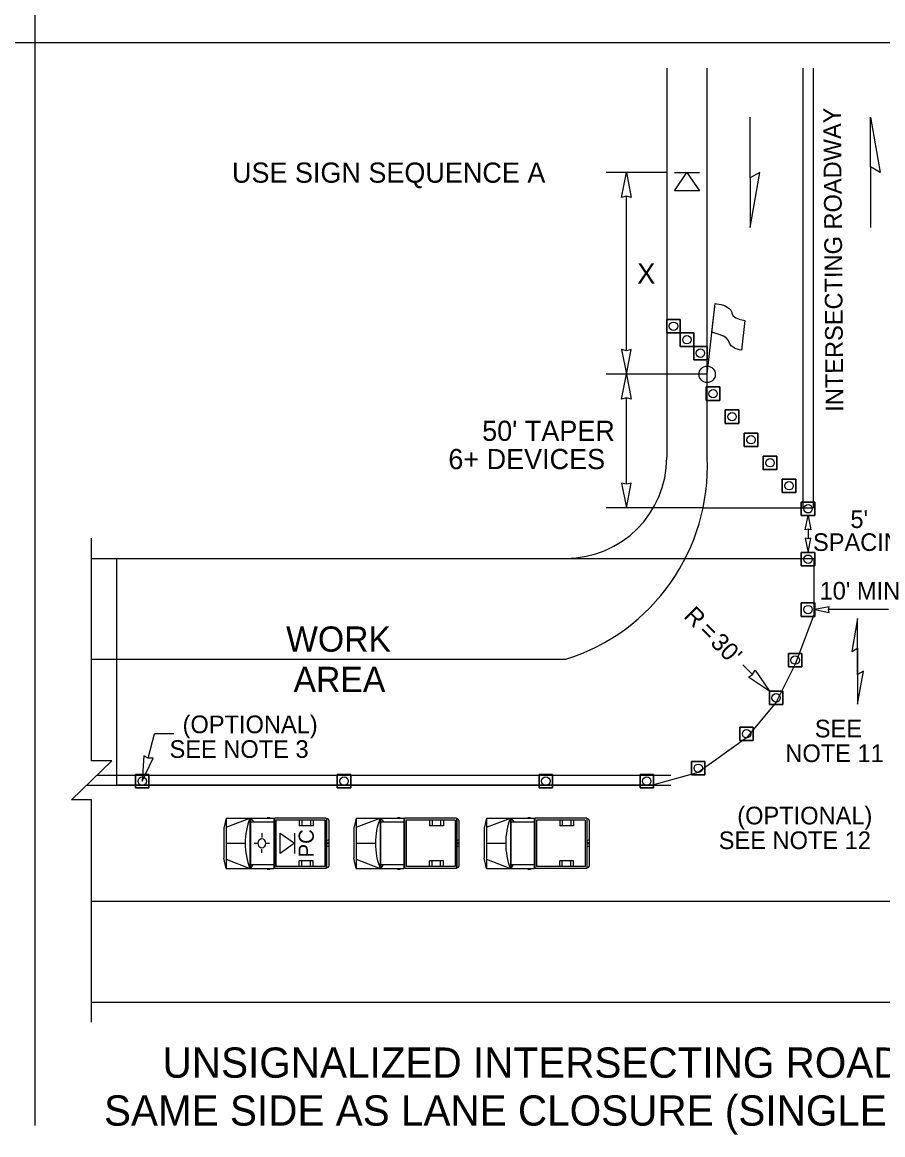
# Model space of a CAD drawing. Extents: x 99999.1 to 100095.7, y 99995 to 100010.7.
# Drawn here: x 100025.2 to 100028.611, y 100001.65 to 100006.062 of the extents above; entities that cross this region are included whole.
import ezdxf

# ---------------------------------------------------------------- set-up
doc = ezdxf.new("R2010")
doc.units = 0
for name, color, linetype in [('RD_ED_ShoulderPavedEdge', 7, 'Continuous'), ('RD_MK_LineDblYellowCenter', 7, 'Continuous'), ('RD_MK_LineEdgeWhite', 7, 'Continuous'), ('RD_MK_LineStop', 7, 'Continuous'), ('SH_DE_DetailBody1Text', 7, 'Continuous'), ('SH_DE_DetailHeading2Text', 7, 'Continuous'), ('TR_WZ_FlaggingStation', 7, 'Continuous'), ('TR_WZ_MotoristVehicle', 7, 'Continuous'), ('TR_WZ_PortableSignMountBlk-Org', 7, 'Continuous'), ('TR_WZ_PortableSignMountBlk-Wht', 7, 'Continuous'), ('TR_WZ_TrafficCone', 7, 'Continuous'), ('TR_WZ_WorkAreaLabel', 7, 'Continuous'), ('TR_WZ_WorkZoneDetails', 7, 'Continuous'), ('TR_WZ_WorkZoneTextCurrent', 7, 'Continuous')]:
    doc.layers.add(name, color=color, linetype=linetype)

msp = doc.modelspace()

# ---------------------------------------------------------------- linework, layer by layer
at = {"layer": 'RD_ED_ShoulderPavedEdge'}
for p, q in [((100025.475, 100003.9359), (100027.355, 100003.9359)), ((100025.475, 100002.1759), (100030.275, 100002.1759))]:
    msp.add_line(p, q, dxfattribs=at)
msp.add_lwpolyline([(100027.755, 100005.8804), (100027.755, 100004.3359)], dxfattribs=at)
msp.add_arc((100027.355, 100004.3359), 0.4, 270, 0, dxfattribs=at)
at = {"layer": 'RD_MK_LineDblYellowCenter'}
for p, q in [((100028.295, 100005.8804), (100028.295, 100004.1359)), ((100028.335, 100005.8804), (100028.335, 100004.1359)), ((100025.4957, 100003.0759), (100027.7712, 100003.0759)), ((100025.4543, 100003.0359), (100027.7712, 100003.0359))]:
    msp.add_line(p, q, dxfattribs=at)
at = {"layer": 'RD_MK_LineEdgeWhite'}
for p, q in [((100027.915, 100004.3359), (100027.915, 100005.8804)), ((100025.475, 100003.5359), (100027.355, 100003.5359)), ((100025.475, 100002.5759), (100030.275, 100002.5759))]:
    msp.add_line(p, q, dxfattribs=at)
msp.add_arc((100027.1158, 100004.2993), 0.8, 287.3948, 2.6212, dxfattribs=at)
at = {"layer": 'RD_MK_LineStop'}
msp.add_line((100027.899, 100004.1359), (100028.335, 100004.1359), dxfattribs=at)
at = {"layer": 'TR_WZ_FlaggingStation'}
for p, q in [((100027.915, 100004.6659), (100027.9471, 100004.9468)), ((100027.934, 100004.8328), (100027.9471, 100004.9471)), ((100028.065, 100004.8793), (100028.0517, 100004.7621)), ((100027.934, 100004.8328), (100027.934, 100004.8328))]:
    msp.add_line(p, q, dxfattribs=at)
for points in [[(100027.9471, 100004.9471), (100027.9528, 100004.9459), (100027.9707, 100004.9424), (100027.9845, 100004.9383), (100027.9942, 100004.9322), (100028.0027, 100004.9275), (100028.0084, 100004.9206), (100028.0126, 100004.9128), (100028.0131, 100004.9066), (100028.0185, 100004.8974), (100028.0293, 100004.8899), (100028.0417, 100004.8847), (100028.065, 100004.8793)], [(100028.0517, 100004.7621), (100028.0436, 100004.7636), (100028.0259, 100004.7682), (100028.0103, 100004.7787), (100028.0037, 100004.7893), (100027.9998, 100004.7996), (100027.9907, 100004.8105), (100027.9798, 100004.8167), (100027.9624, 100004.8238), (100027.934, 100004.8328)]]:
    msp.add_lwpolyline(points, dxfattribs=at)
msp.add_circle((100027.915, 100004.6659), 0.0325, dxfattribs=at)
at = {"layer": 'TR_WZ_MotoristVehicle'}
for p, q in [((100026.008, 100002.9059), (100025.9987, 100002.8655)), ((100026.008, 100002.9059), (100026.008, 100002.7059)), ((100026.008, 100002.9059), (100026.1969, 100002.9059)), ((100026.008, 100002.8693), (100026.1025, 100002.9059)), ((100026.1025, 100002.9059), (100026.1025, 100002.7059)), ((100026.1042, 100002.9059), (100026.1042, 100002.7059)), ((100026.1042, 100002.9059), (100026.1162, 100002.8904)), ((100026.1042, 100002.8904), (100026.1969, 100002.8904)), ((100026.1712, 100002.9087), (100026.1825, 100002.9087)), ((100026.1969, 100002.9059), (100026.1969, 100002.7059)), ((100026.4054, 100002.9059), (100026.1997, 100002.9059)), ((100026.1997, 100002.9059), (100026.1997, 100002.7059)), ((100026.3995, 100002.8979), (100026.2055, 100002.8979)), ((100026.2055, 100002.8979), (100026.2055, 100002.7139)), ((100026.2982, 100002.8979), (100026.2982, 100002.8749)), ((100026.3082, 100002.8979), (100026.3082, 100002.8749)), ((100026.3422, 100002.8979), (100026.3422, 100002.8749)), ((100026.3532, 100002.8979), (100026.3532, 100002.8749)), ((100026.3995, 100002.8979), (100026.3995, 100002.7139)), ((100026.4054, 100002.9059), (100026.4054, 100002.7059)), ((100026.4105, 100002.9026), (100026.4061, 100002.9026)), ((100026.4061, 100002.9026), (100026.4061, 100002.7092)), ((100026.415, 100002.8965), (100026.415, 100002.7153)), ((100026.5243, 100002.9059), (100026.515, 100002.8655)), ((100026.5243, 100002.9059), (100026.5243, 100002.7059)), ((100026.5243, 100002.9059), (100026.7132, 100002.9059)), ((100026.5243, 100002.8693), (100026.6187, 100002.9059)), ((100026.6187, 100002.9059), (100026.6187, 100002.7059)), ((100026.6204, 100002.9059), (100026.6204, 100002.7059)), ((100026.6204, 100002.9059), (100026.6325, 100002.8904)), ((100026.6204, 100002.8904), (100026.7132, 100002.8904)), ((100026.6874, 100002.9087), (100026.6987, 100002.9087)), ((100026.7132, 100002.9059), (100026.7132, 100002.7059)), ((100026.9216, 100002.9059), (100026.7159, 100002.9059)), ((100026.7159, 100002.9059), (100026.7159, 100002.7059)), ((100026.9158, 100002.8979), (100026.7218, 100002.8979)), ((100026.7218, 100002.8979), (100026.7218, 100002.7139)), ((100026.8145, 100002.8979), (100026.8145, 100002.8749)), ((100026.8244, 100002.8979), (100026.8244, 100002.8749)), ((100026.8585, 100002.8979), (100026.8585, 100002.8749)), ((100026.8694, 100002.8979), (100026.8694, 100002.8749)), ((100026.9158, 100002.8979), (100026.9158, 100002.7139)), ((100026.9216, 100002.9059), (100026.9216, 100002.7059)), ((100026.9268, 100002.9026), (100026.9223, 100002.9026)), ((100026.9223, 100002.9026), (100026.9223, 100002.7092)), ((100026.9313, 100002.8965), (100026.9313, 100002.7153)), ((100027.0405, 100002.9059), (100027.0313, 100002.8655)), ((100027.0405, 100002.9059), (100027.0405, 100002.7059)), ((100027.0405, 100002.9059), (100027.2294, 100002.9059)), ((100027.0405, 100002.8693), (100027.135, 100002.9059)), ((100027.135, 100002.9059), (100027.135, 100002.7059)), ((100027.1367, 100002.9059), (100027.1367, 100002.7059)), ((100027.1367, 100002.9059), (100027.1487, 100002.8904)), ((100027.1367, 100002.8904), (100027.2294, 100002.8904)), ((100027.2037, 100002.9087), (100027.215, 100002.9087)), ((100027.2294, 100002.9059), (100027.2294, 100002.7059)), ((100027.4379, 100002.9059), (100027.2322, 100002.9059)), ((100027.2322, 100002.9059), (100027.2322, 100002.7059)), ((100027.4321, 100002.8979), (100027.238, 100002.8979)), ((100027.238, 100002.8979), (100027.238, 100002.7139)), ((100027.3308, 100002.8979), (100027.3308, 100002.8749)), ((100027.3407, 100002.8979), (100027.3407, 100002.8749)), ((100027.3747, 100002.8979), (100027.3747, 100002.8749)), ((100027.3857, 100002.8979), (100027.3857, 100002.8749)), ((100027.4321, 100002.8979), (100027.4321, 100002.7139)), ((100027.4379, 100002.9059), (100027.4379, 100002.7059)), ((100027.4431, 100002.9026), (100027.4386, 100002.9026)), ((100027.4386, 100002.9026), (100027.4386, 100002.7092)), ((100027.4475, 100002.8965), (100027.4475, 100002.7153)), ((100025.9987, 100002.8655), (100025.9987, 100002.7463)), ((100026.1495, 100002.8455), (100026.1495, 100002.8294)), ((100026.3532, 100002.8749), (100026.2982, 100002.8749)), ((100026.515, 100002.8655), (100026.515, 100002.7463)), ((100026.8694, 100002.8749), (100026.8145, 100002.8749)), ((100027.0313, 100002.8655), (100027.0313, 100002.7463)), ((100027.3857, 100002.8749), (100027.3308, 100002.8749)), ((100026.008, 100002.8059), (100026.0839, 100002.8059)), ((100026.1194, 100002.806), (100026.132, 100002.806)), ((100026.1636, 100002.8056), (100026.1636, 100002.8056)), ((100026.1804, 100002.8051), (100026.1655, 100002.8055)), ((100026.415, 100002.82), (100026.4061, 100002.8162)), ((100026.415, 100002.7918), (100026.4061, 100002.7956)), ((100026.4126, 100002.8059), (100026.4085, 100002.8059)), ((100026.4105, 100002.8087), (100026.4105, 100002.8031)), ((100026.5243, 100002.8059), (100026.6002, 100002.8059)), ((100026.9313, 100002.82), (100026.9223, 100002.8162)), ((100026.9313, 100002.7918), (100026.9223, 100002.7956)), ((100026.9289, 100002.8059), (100026.9247, 100002.8059)), ((100026.9268, 100002.8087), (100026.9268, 100002.8031)), ((100027.0405, 100002.8059), (100027.1164, 100002.8059)), ((100027.4475, 100002.82), (100027.4386, 100002.8162)), ((100027.4475, 100002.7918), (100027.4386, 100002.7956)), ((100027.4451, 100002.8059), (100027.441, 100002.8059)), ((100027.4431, 100002.8087), (100027.4431, 100002.8031)), ((100026.008, 100002.7059), (100025.9987, 100002.7463)), ((100026.1502, 100002.7674), (100026.1499, 100002.7825)), ((100026.5243, 100002.7059), (100026.515, 100002.7463)), ((100027.0405, 100002.7059), (100027.0313, 100002.7463)), ((100026.008, 100002.7425), (100026.1025, 100002.7059)), ((100026.008, 100002.7059), (100026.1969, 100002.7059)), ((100026.1042, 100002.7214), (100026.1969, 100002.7214)), ((100026.1141, 100002.7214), (100026.1042, 100002.7059)), ((100026.1712, 100002.7031), (100026.1825, 100002.7031)), ((100026.4054, 100002.7059), (100026.1997, 100002.7059)), ((100026.3995, 100002.7139), (100026.2055, 100002.7139)), ((100026.2982, 100002.7139), (100026.2982, 100002.7369)), ((100026.3532, 100002.7369), (100026.2982, 100002.7369)), ((100026.3082, 100002.7139), (100026.3082, 100002.7369)), ((100026.3422, 100002.7139), (100026.3422, 100002.7369)), ((100026.3532, 100002.7139), (100026.3532, 100002.7369)), ((100026.4105, 100002.7092), (100026.4061, 100002.7092)), ((100026.5243, 100002.7425), (100026.6187, 100002.7059)), ((100026.5243, 100002.7059), (100026.7132, 100002.7059)), ((100026.6204, 100002.7214), (100026.7132, 100002.7214)), ((100026.6304, 100002.7214), (100026.6204, 100002.7059)), ((100026.6874, 100002.7031), (100026.6987, 100002.7031)), ((100026.9216, 100002.7059), (100026.7159, 100002.7059)), ((100026.9158, 100002.7139), (100026.7218, 100002.7139)), ((100026.8145, 100002.7139), (100026.8145, 100002.7369)), ((100026.8694, 100002.7369), (100026.8145, 100002.7369)), ((100026.8244, 100002.7139), (100026.8244, 100002.7369)), ((100026.8585, 100002.7139), (100026.8585, 100002.7369)), ((100026.8694, 100002.7139), (100026.8694, 100002.7369)), ((100026.9268, 100002.7092), (100026.9223, 100002.7092)), ((100027.0405, 100002.7425), (100027.135, 100002.7059)), ((100027.0405, 100002.7059), (100027.2294, 100002.7059)), ((100027.1367, 100002.7214), (100027.2294, 100002.7214)), ((100027.1467, 100002.7214), (100027.1367, 100002.7059)), ((100027.2037, 100002.7031), (100027.215, 100002.7031)), ((100027.4379, 100002.7059), (100027.2322, 100002.7059)), ((100027.4321, 100002.7139), (100027.238, 100002.7139)), ((100027.3308, 100002.7139), (100027.3308, 100002.7369)), ((100027.3857, 100002.7369), (100027.3308, 100002.7369)), ((100027.3407, 100002.7139), (100027.3407, 100002.7369)), ((100027.3747, 100002.7139), (100027.3747, 100002.7369)), ((100027.3857, 100002.7139), (100027.3857, 100002.7369)), ((100027.4431, 100002.7092), (100027.4386, 100002.7092))]:
    msp.add_line(p, q, dxfattribs=at)
for centre, major_axis, start_param, end_param in [((100026.2374, 100002.8059), (0, -0.2099), 4.215667, 5.208926), ((100026.4105, 100002.8965), (0, 0.0061), 4.712389, 6.283185), ((100026.7537, 100002.8059), (0, -0.2099), 4.215667, 5.208926), ((100026.9268, 100002.8965), (0, 0.0061), 4.712389, 6.283185), ((100027.27, 100002.8059), (0, -0.2099), 4.215667, 5.208926), ((100027.4431, 100002.8965), (0, 0.0061), 4.712389, 6.283185), ((100026.4105, 100002.7153), (0, -0.0061), 0, 1.570796), ((100026.9268, 100002.7153), (0, -0.0061), 0, 1.570796), ((100027.4431, 100002.7153), (0, -0.0061), 0, 1.570796)]:
    msp.add_ellipse(centre, major_axis=major_axis, ratio=0.73155, start_param=start_param, end_param=end_param, dxfattribs=at)
for centre, major_axis in [((100026.1495, 100002.8059), (0, 0.0193)), ((100026.4105, 100002.8059), (0, 0.00282)), ((100026.9268, 100002.8059), (0, 0.00282)), ((100027.4431, 100002.8059), (0, 0.00282))]:
    msp.add_ellipse(centre, major_axis=major_axis, ratio=0.73155, dxfattribs=at)
at = {"layer": 'TR_WZ_PortableSignMountBlk-Org'}
msp.add_line((100027.785, 100005.4659), (100027.885, 100005.4659), dxfattribs=at)
msp.add_lwpolyline([(100027.8349, 100005.4659), (100027.885, 100005.3941), (100027.785, 100005.3941)], close=True, dxfattribs=at)
at = {"layer": 'TR_WZ_PortableSignMountBlk-Wht'}
msp.add_line((100026.2793, 100002.8458), (100026.2793, 100002.7658), dxfattribs=at)
msp.add_lwpolyline([(100026.2793, 100002.8059), (100026.2219, 100002.7658), (100026.2219, 100002.8458)], close=True, dxfattribs=at)
at = {"layer": 'TR_WZ_TrafficCone'}
for points in [[(100027.8083, 100004.8833), (100027.8083, 100004.8299), (100027.755, 100004.8299), (100027.755, 100004.8833), (100027.8083, 100004.8833)], [(100027.755, 100004.8833), (100027.755, 100004.8299), (100027.8083, 100004.8299), (100027.8083, 100004.8833), (100027.755, 100004.8833)], [(100027.8617, 100004.8299), (100027.8617, 100004.7766), (100027.8083, 100004.7766), (100027.8083, 100004.8299), (100027.8617, 100004.8299)], [(100027.8083, 100004.8299), (100027.8083, 100004.7766), (100027.8617, 100004.7766), (100027.8617, 100004.8299), (100027.8083, 100004.8299)], [(100027.915, 100004.7766), (100027.915, 100004.7233), (100027.8617, 100004.7233), (100027.8617, 100004.7766), (100027.915, 100004.7766)], [(100027.8617, 100004.7766), (100027.8617, 100004.7233), (100027.915, 100004.7233), (100027.915, 100004.7766), (100027.8617, 100004.7766)], [(100027.9117, 100004.6159), (100027.965, 100004.6159), (100027.965, 100004.5626), (100027.9117, 100004.5626), (100027.9117, 100004.6159)], [(100027.9117, 100004.5626), (100027.965, 100004.5626), (100027.965, 100004.6159), (100027.9117, 100004.6159), (100027.9117, 100004.5626)], [(100027.987, 100004.5246), (100028.0404, 100004.5246), (100028.0404, 100004.4712), (100027.987, 100004.4712), (100027.987, 100004.5246)], [(100027.987, 100004.4712), (100028.0404, 100004.4712), (100028.0404, 100004.5246), (100027.987, 100004.5246), (100027.987, 100004.4712)], [(100028.0624, 100004.4332), (100028.1157, 100004.4332), (100028.1157, 100004.3799), (100028.0624, 100004.3799), (100028.0624, 100004.4332)], [(100028.0624, 100004.3799), (100028.1157, 100004.3799), (100028.1157, 100004.4332), (100028.0624, 100004.4332), (100028.0624, 100004.3799)], [(100028.1377, 100004.3419), (100028.191, 100004.3419), (100028.191, 100004.2886), (100028.1377, 100004.2886), (100028.1377, 100004.3419)], [(100028.1377, 100004.2886), (100028.191, 100004.2886), (100028.191, 100004.3419), (100028.1377, 100004.3419), (100028.1377, 100004.2886)], [(100028.213, 100004.2506), (100028.2664, 100004.2506), (100028.2664, 100004.1972), (100028.213, 100004.1972), (100028.213, 100004.2506)], [(100028.213, 100004.1972), (100028.2664, 100004.1972), (100028.2664, 100004.2506), (100028.213, 100004.2506), (100028.213, 100004.1972)], [(100028.2884, 100004.1592), (100028.3417, 100004.1592), (100028.3417, 100004.1059), (100028.2884, 100004.1059), (100028.2884, 100004.1592)], [(100028.2884, 100004.1059), (100028.3417, 100004.1059), (100028.3417, 100004.1592), (100028.2884, 100004.1592), (100028.2884, 100004.1059)], [(100028.2884, 100003.9592), (100028.3417, 100003.9592), (100028.3417, 100003.9059), (100028.2884, 100003.9059), (100028.2884, 100003.9592)], [(100028.2884, 100003.9059), (100028.3417, 100003.9059), (100028.3417, 100003.9592), (100028.2884, 100003.9592), (100028.2884, 100003.9059)], [(100028.2884, 100003.7592), (100028.3417, 100003.7592), (100028.3417, 100003.7059), (100028.2884, 100003.7059), (100028.2884, 100003.7592)], [(100028.2884, 100003.7059), (100028.3417, 100003.7059), (100028.3417, 100003.7592), (100028.2884, 100003.7592), (100028.2884, 100003.7059)], [(100028.2373, 100003.5592), (100028.2907, 100003.5592), (100028.2907, 100003.5059), (100028.2373, 100003.5059), (100028.2373, 100003.5592)], [(100028.2373, 100003.5059), (100028.2907, 100003.5059), (100028.2907, 100003.5592), (100028.2373, 100003.5592), (100028.2373, 100003.5059)], [(100028.1617, 100003.4093), (100028.215, 100003.4093), (100028.215, 100003.3559), (100028.1617, 100003.3559), (100028.1617, 100003.4093)], [(100028.1617, 100003.3559), (100028.215, 100003.3559), (100028.215, 100003.4093), (100028.1617, 100003.4093), (100028.1617, 100003.3559)], [(100028.0447, 100003.267), (100028.0981, 100003.267), (100028.0981, 100003.2136), (100028.0447, 100003.2136), (100028.0447, 100003.267)], [(100028.0447, 100003.2136), (100028.0981, 100003.2136), (100028.0981, 100003.267), (100028.0447, 100003.267), (100028.0447, 100003.2136)], [(100027.853, 100003.1302), (100027.9064, 100003.1302), (100027.9064, 100003.0768), (100027.853, 100003.0768), (100027.853, 100003.1302)], [(100027.853, 100003.0768), (100027.9064, 100003.0768), (100027.9064, 100003.1302), (100027.853, 100003.1302), (100027.853, 100003.0768)], [(100025.649, 100003.0792), (100025.7024, 100003.0792), (100025.7024, 100003.0259), (100025.649, 100003.0259), (100025.649, 100003.0792)], [(100025.649, 100003.0259), (100025.7024, 100003.0259), (100025.7024, 100003.0792), (100025.649, 100003.0792), (100025.649, 100003.0259)], [(100026.449, 100003.0792), (100026.5024, 100003.0792), (100026.5024, 100003.0259), (100026.449, 100003.0259), (100026.449, 100003.0792)], [(100026.449, 100003.0259), (100026.5024, 100003.0259), (100026.5024, 100003.0792), (100026.449, 100003.0792), (100026.449, 100003.0259)], [(100027.249, 100003.0792), (100027.3024, 100003.0792), (100027.3024, 100003.0259), (100027.249, 100003.0259), (100027.249, 100003.0792)], [(100027.249, 100003.0259), (100027.3024, 100003.0259), (100027.3024, 100003.0792), (100027.249, 100003.0792), (100027.249, 100003.0259)], [(100027.649, 100003.0792), (100027.7024, 100003.0792), (100027.7024, 100003.0259), (100027.649, 100003.0259), (100027.649, 100003.0792)], [(100027.649, 100003.0259), (100027.7024, 100003.0259), (100027.7024, 100003.0792), (100027.649, 100003.0792), (100027.649, 100003.0259)]]:
    msp.add_lwpolyline(points, dxfattribs=at)
for centre in [(100027.7817, 100004.8566), (100027.835, 100004.8033), (100027.8883, 100004.7499), (100027.9384, 100004.5892), (100028.0137, 100004.4979), (100028.089, 100004.4066), (100028.1644, 100004.3152), (100028.2397, 100004.2239), (100028.315, 100004.1326), (100028.315, 100003.9326), (100028.315, 100003.7326), (100028.264, 100003.5326), (100028.1883, 100003.3826), (100028.0714, 100003.2403), (100027.8797, 100003.1035), (100025.6757, 100003.0526), (100026.4757, 100003.0526), (100027.2757, 100003.0526), (100027.6757, 100003.0526)]:
    msp.add_circle(centre, 0.0167, dxfattribs=at)
at = {"layer": 'TR_WZ_WorkZoneDetails'}
for p, q in [((100025.25, 100010.275), (100025.25, 100001.6859)), ((100025.25, 100005.9804), (100020, 100005.9804)), ((100030.5, 100005.9804), (100025.25, 100005.9804)), ((100028.0855, 100005.4448), (100028.0855, 100005.6859)), ((100028.5627, 100005.4894), (100028.5627, 100005.2483)), ((100027.755, 100005.4659), (100027.515, 100005.4659)), ((100027.595, 100004.7596), (100027.595, 100005.3722)), ((100027.915, 100004.6659), (100027.515, 100004.6659)), ((100027.595, 100004.2296), (100027.595, 100004.5722)), ((100027.899, 100004.1359), (100027.515, 100004.1359)), ((100028.3151, 100004.0514), (100028.3151, 100004.0137)), ((100028.6338, 100003.7326), (100028.3962, 100003.7326)), ((100028.5115, 100003.4752), (100028.5115, 100003.6199)), ((100028.5115, 100003.5799), (100028.5115, 100003.4352)), ((100028.0954, 100003.4755), (100028.057, 100003.514)), ((100025.6993, 100003.1433), (100025.7245, 100003.2406)), ((100025.8007, 100003.2406), (100025.7245, 100003.2406))]:
    msp.add_line(p, q, dxfattribs=at)
for points in [[(100028.5627, 100005.6859), (100028.6013, 100005.4671), (100028.5627, 100005.4894)], [(100027.595, 100005.4659), (100027.6143, 100005.3676), (100027.595, 100005.3722), (100027.5757, 100005.3676)], [(100028.0855, 100005.2483), (100028.124, 100005.4671), (100028.0855, 100005.4448)], [(100027.595, 100004.6659), (100027.6143, 100004.7642), (100027.595, 100004.7596), (100027.5757, 100004.7642)], [(100027.595, 100004.6659), (100027.6143, 100004.5676), (100027.595, 100004.5722), (100027.5757, 100004.5676)], [(100027.595, 100004.1359), (100027.6143, 100004.2342), (100027.595, 100004.2296), (100027.5757, 100004.2342)], [(100028.315, 100004.1059), (100028.3263, 100004.0487), (100028.315, 100004.0514), (100028.3038, 100004.0487)], [(100028.3151, 100003.9592), (100028.3263, 100004.0164), (100028.3151, 100004.0137), (100028.3039, 100004.0164)], [(100028.3383, 100003.9359), (100028.3383, 100003.7126), (100028.264, 100003.5159), (100028.1883, 100003.3659), (100028.1883, 100003.3659), (100028.1883, 100003.3659), (100028.0714, 100003.2236), (100028.0714, 100003.2236), (100028.0714, 100003.2236), (100027.8797, 100003.0868), (100027.699, 100003.0359), (100026.499, 100003.0359), (100025.699, 100003.0359), (100025.575, 100003.0359), (100025.575, 100003.9359)], [(100028.3417, 100003.7326), (100028.3989, 100003.7214), (100028.3962, 100003.7326), (100028.3989, 100003.7438)], [(100028.5115, 100003.6978), (100028.4883, 100003.5665), (100028.5115, 100003.5799)], [(100028.1617, 100003.4093), (100028.0786, 100003.4652), (100028.0954, 100003.4756), (100028.1058, 100003.4924)], [(100028.5115, 100003.3573), (100028.5346, 100003.4886), (100028.5115, 100003.4752)], [(100025.6757, 100003.0526), (100025.719, 100003.1429), (100025.6992, 100003.1433), (100025.6817, 100003.1525)]]:
    msp.add_lwpolyline(points, close=True, dxfattribs=at)
msp.add_lwpolyline([(100025.475, 100002.0959), (100025.475, 100002.9785), (100025.395, 100002.9785), (100025.555, 100003.1333), (100025.475, 100003.1333), (100025.475, 100004.0159)], dxfattribs=at)

# ---------------------------------------------------------------- texts
at = {"layer": 'SH_DE_DetailBody1Text'}
msp.add_text('INTERSECTING ROADWAY', height=0.07, rotation=90.4626, dxfattribs=at).set_placement((100028.455, 100004.5177))
at = {"layer": 'SH_DE_DetailHeading2Text'}
for s, p in [('UNSIGNALIZED INTERSECTING ROADWAY DETAIL', (100025.7563, 100001.8759)), ('SAME SIDE AS LANE CLOSURE (SINGLE OPEN LANE)', (100025.524, 100001.6859))]:
    msp.add_text(s, height=0.12, rotation=360, dxfattribs=at).set_placement(p)
at = {"layer": 'TR_WZ_MotoristVehicle'}
msp.add_text('PC', height=0.06, rotation=90, dxfattribs=at).set_placement((100026.3557, 100002.7499))
at = {"layer": 'TR_WZ_WorkAreaLabel'}
for s, p in [('WORK', (100026.2458, 100003.5659)), ('AREA', (100026.2754, 100003.4059))]:
    msp.add_text(s, height=0.1, dxfattribs=at).set_placement(p)
at = {"layer": 'TR_WZ_WorkZoneTextCurrent'}
for s, height, p in [('USE SIGN SEQUENCE A', 0.08, (100026.0313, 100005.4259)), ('X', 0.08, (100027.6379, 100005.0259)), ("50' TAPER", 0.08, (100027.0232, 100004.4019)), ('6+ DEVICES', 0.08, (100026.8892, 100004.2899)), ("5'", 0.07, (100028.483, 100004.0564)), ('SPACING', 0.07, (100028.3346, 100003.9654)), ("10' MIN", 0.07, (100028.3608, 100003.7726)), ('(OPTIONAL)', 0.07, (100025.8355, 100003.2426)), ('SEE', 0.07, (100028.3418, 100003.2259)), ('SEE NOTE 3', 0.07, (100025.7838, 100003.1446)), ('NOTE 11', 0.07, (100028.225, 100003.1279)), ('(OPTIONAL)', 0.07, (100028.0344, 100002.8808)), ('SEE NOTE 12', 0.07, (100027.961, 100002.7828))]:
    msp.add_text(s, height=height, dxfattribs=at).set_placement(p)
for s, p in [('R', (100027.8182, 100003.7032)), ('=', (100027.8774, 100003.644)), ("30'", (100027.9242, 100003.5972))]:
    msp.add_text(s, height=0.07, rotation=315, dxfattribs=at).set_placement(p)

doc.saveas('drawing.dxf')
